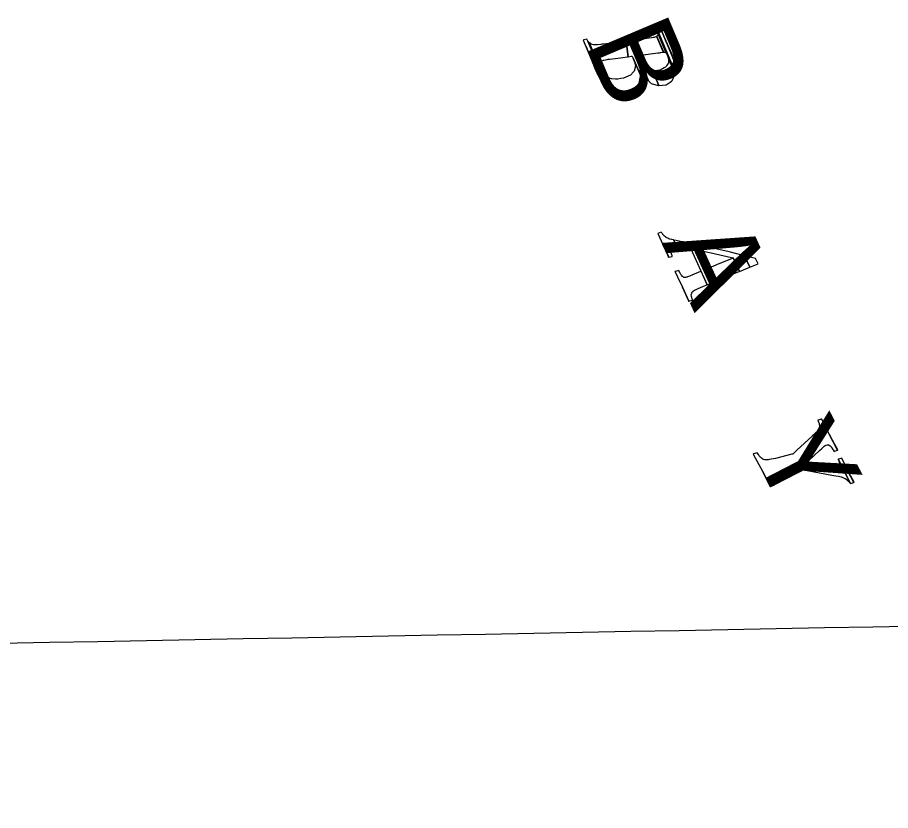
# Model space of a CAD drawing. Extents: x 3962991 to 3983549, y 181631 to 204078.
# Drawn here: x 3975675 to 3976425, y 194348 to 195029 of the extents above; entities that cross this region are included whole.
import ezdxf

# ---------------------------------------------------------------- set-up
doc = ezdxf.new("R2010")
doc.units = 0
for name, color, linetype in [('V-ANNO-MASK', 7, 'Continuous'), ('V-ANNO-MASK2', 7, 'Continuous'), ('V-GRID-MAJR', 7, 'Continuous'), ('V-RIVR-IDEN', 7, 'Continuous')]:
    doc.layers.add(name, color=color, linetype=linetype)

msp = doc.modelspace()

# ---------------------------------------------------------------- linework, layer by layer
at = {"layer": 'V-ANNO-MASK2'}
for points in [[(3976224.33, 195020.65), (3976225.16, 195018.1), (3976240.52, 194981.73), (3976240.5, 194982.35), (3976240.5, 194982.41), (3976223.81, 195021.93)], [(3976226.28, 195022.57), (3976223.82, 195021.92), (3976240.5, 194982.41), (3976240.32, 194989.32), (3976238.28, 194995.67), (3976229.42, 195016.66), (3976228.97, 195017.89), (3976227.19, 195022.8), (3976226.92, 195022.74), (3976226.86, 195022.72)], [(3976200.09, 194995.68), (3976202.73, 194996.02), (3976203.2, 194996.08), (3976203.48, 194996.11), (3976203.65, 194996.13), (3976204.46, 194994.33), (3976210.61, 194979.78), (3976210.41, 194984.09), (3976214.13, 194978.38), (3976216.68, 194975.9), (3976208.94, 194994.22), (3976207.99, 194996.61), (3976208.47, 194996.68), (3976209.74, 194996.84), (3976210.44, 194996.93), (3976214.86, 194997.5), (3976215.26, 194997.56), (3976221.3, 194998.33), (3976221.48, 194998.36), (3976225.57, 194998.89), (3976227.07, 194999.08), (3976227.71, 194999.16), (3976228.03, 194999.2), (3976230.05, 194999.46), (3976230.07, 194999.47), (3976230.69, 194999.51), (3976224.83, 195013.39), (3976224.38, 195012.93), (3976224.36, 195012.93), (3976222.52, 195012.25), (3976222.2, 195012.19), (3976221.59, 195012.07), (3976220.12, 195011.8), (3976216.03, 195011.28), (3976215.84, 195011.25), (3976209.8, 195010.47), (3976209.41, 195010.42), (3976204.99, 195009.85), (3976204.28, 195009.76), (3976203.02, 195009.59), (3976202.53, 195009.53), (3976202.48, 195009.53), (3976201.05, 195009.34), (3976199.81, 195009.18), (3976198.27, 195008.98)], [(3976224.83, 195013.39), (3976224.38, 195012.93), (3976230.07, 194999.47), (3976230.69, 194999.51), (3976231.32, 194999.55), (3976231.62, 194999.42), (3976231.61, 194999.43), (3976232.58, 194999), (3976232.84, 194998.64), (3976225.6, 195015.78), (3976225.58, 195015.57), (3976225.45, 195014.02), (3976225.28, 195013.85)], [(3976225.54, 195016.09), (3976225.6, 195015.77), (3976232.84, 194998.64), (3976233.03, 194998.36), (3976233.47, 194997.71), (3976233.66, 194997.44), (3976240.54, 194981.17), (3976240.52, 194981.73), (3976225.16, 195018.11), (3976225.34, 195017.15), (3976225.4, 195016.83)], [(3976233.8, 195006.45), (3976229.42, 195016.66), (3976238.28, 194995.68), (3976238.04, 194996.41), (3976237.5, 194998.12), (3976237.49, 194998.13)], [(3976161.45, 195010), (3976161.29, 195009.97), (3976163.83, 195004.35), (3976164.2, 195003.55), (3976174.11, 194980.08), (3976177.54, 194973.53), (3976182.23, 194968.45), (3976182.87, 194967.75), (3976165.39, 195009.14), (3976164.42, 195010.62), (3976162.08, 195010.13), (3976161.48, 195009.99)], [(3976170.58, 194987.97), (3976172.33, 194983.47), (3976173.1, 194982.02), (3976173.99, 194980.32), (3976174.11, 194980.08), (3976164.2, 195003.55), (3976168.54, 194993.22)], [(3976166.61, 195007.76), (3976165.38, 195009.15), (3976182.87, 194967.75), (3976184.06, 194966.46)], [(3976198.27, 195008.98), (3976198.22, 195008.97), (3976198.06, 195008.95), (3976197.78, 195008.92), (3976197.31, 195008.86), (3976194.66, 195008.52), (3976193.76, 195008.4), (3976190.08, 195007.93), (3976188.09, 195007.67), (3976183.48, 195007.08), (3976181.07, 195006.76), (3976178.57, 195006.43), (3976177.35, 195006.3), (3976176.45, 195006.2), (3976173.7, 195005.88), (3976173.65, 195005.88), (3976173.13, 195005.88), (3976172.08, 195005.86), (3976170.9, 195005.85), (3976170.36, 195005.83), (3976169.09, 195006.22), (3976168.53, 195006.39), (3976168.08, 195006.52), (3976167.65, 195006.88), (3976166.92, 195007.5), (3976166.81, 195007.6), (3976166.77, 195007.63), (3976166.62, 195007.75), (3976184.06, 194966.46), (3976184.24, 194966.27), (3976176.14, 194985.45), (3976176.11, 194985.57), (3976176.03, 194985.94), (3976175.51, 194988.27), (3976175.57, 194988.77), (3976175.66, 194989.5), (3976175.77, 194990.4), (3976176.51, 194991.28), (3976176.87, 194991.7), (3976177.86, 194992.18), (3976178.74, 194992.59), (3976179.21, 194992.71), (3976179.26, 194992.71), (3976181.9, 194993.31), (3976182.78, 194993.42), (3976184, 194993.58), (3976184, 194993.59), (3976186.5, 194993.91), (3976188.91, 194994.22), (3976193.52, 194994.82), (3976195.51, 194995.07), (3976195.5, 194995.08), (3976199.18, 194995.55), (3976200.09, 194995.68)], [(3976234, 194996.46), (3976234.8, 194994.16), (3976240.45, 194980.79), (3976240.54, 194980.97), (3976240.54, 194981.17), (3976233.66, 194997.44)], [(3976178.58, 194981.01), (3976177.6, 194982.22), (3976184.37, 194966.18), (3976184.95, 194965.93), (3976185.28, 194965.79), (3976185.77, 194965.57), (3976186.37, 194965.31), (3976187.73, 194964.71), (3976187.73, 194964.72), (3976188.4, 194964.42), (3976189.85, 194963.79), (3976191.15, 194963.23), (3976191.79, 194962.94), (3976191.83, 194962.95), (3976194.71, 194962.97), (3976195.65, 194962.97), (3976196.93, 194962.98), (3976199.56, 194963), (3976201.67, 194964.01), (3976205.72, 194965.94), (3976206.99, 194967.9), (3976209.34, 194971.5), (3976209.64, 194973.06), (3976210.51, 194977.6), (3976210.67, 194978.4), (3976210.63, 194979.18), (3976210.61, 194979.64), (3976210.61, 194979.78), (3976204.46, 194994.33), (3976204.71, 194993.62), (3976205.6, 194991.11), (3976205.85, 194989.82), (3976206.26, 194987.66), (3976205.33, 194983.27), (3976204.66, 194982.58), (3976201.98, 194979.76), (3976200.2, 194979.01), (3976196.08, 194977.24), (3976193.7, 194976.87), (3976191.23, 194976.46), (3976190.03, 194976.27), (3976189.05, 194976.37), (3976186.03, 194976.7), (3976185.98, 194976.7), (3976185.43, 194976.75), (3976184.33, 194976.87), (3976182.77, 194977.74), (3976182.06, 194978.13), (3976180.61, 194978.94), (3976179.97, 194979.29), (3976179.14, 194980.32)], [(3976209.17, 194993.8), (3976208.94, 194994.22), (3976216.68, 194975.9), (3976216.76, 194975.83), (3976217.64, 194974.98), (3976211.56, 194989.37)], [(3976214.06, 194986.61), (3976211.57, 194989.36), (3976217.64, 194974.98), (3976219.9, 194972.77), (3976220.76, 194972.51), (3976226.14, 194970.8), (3976226.54, 194970.84), (3976221.29, 194983.27), (3976220.81, 194983.41), (3976215.45, 194985.08)], [(3976227.31, 194984.08), (3976221.3, 194983.26), (3976226.54, 194970.84), (3976232.62, 194971.53), (3976232.77, 194971.64), (3976236.12, 194973.92), (3976237.35, 194974.76), (3976237.87, 194975.11), (3976238.04, 194975.5), (3976239.15, 194977.92), (3976239.16, 194977.95), (3976239.49, 194978.68), (3976239.82, 194979.41), (3976239.95, 194979.69), (3976240.36, 194980.59), (3976240.41, 194980.7), (3976240.45, 194980.79), (3976234.8, 194994.18), (3976234.79, 194994.01), (3976234.78, 194993.8), (3976234.7, 194992.11), (3976234.68, 194991.59), (3976234.62, 194990.21), (3976234.22, 194989.64), (3976234.21, 194989.61), (3976232.9, 194987.69), (3976232.68, 194987.37), (3976232.28, 194986.76), (3976231, 194986.06), (3976227.5, 194984.1)], [(3976176.5, 194984.65), (3976176.14, 194985.45), (3976184.24, 194966.27), (3976184.28, 194966.22), (3976184.37, 194966.18), (3976177.6, 194982.23)], [(3976225.69, 194843.84), (3976225.51, 194843.75), (3976229.97, 194834.47), (3976235.02, 194823.43), (3976237.96, 194824.21), (3976237.73, 194824.89), (3976237.49, 194825.57), (3976237.24, 194826.45), (3976237.2, 194826.59), (3976237.12, 194826.88), (3976236.87, 194827.76), (3976236.85, 194827.9), (3976236.78, 194828.71), (3976236.77, 194828.79), (3976236.68, 194829.81), (3976236.68, 194829.87), (3976236.89, 194830.45), (3976237.05, 194830.91), (3976237.17, 194831.24), (3976237.41, 194831.43), (3976237.92, 194831.79), (3976238.43, 194832.15), (3976238.51, 194832.2), (3976239.09, 194832.35), (3976240.08, 194832.59), (3976240.24, 194832.62), (3976241.6, 194832.54), (3976241.86, 194832.53), (3976239.24, 194838.25), (3976238.96, 194838.32), (3976237.45, 194838.73), (3976237.25, 194838.78), (3976236, 194839.1), (3976235.26, 194839.3), (3976235.15, 194839.34), (3976234.29, 194839.73), (3976233.43, 194840.14), (3976233.02, 194840.34), (3976232.67, 194840.5), (3976232.07, 194840.98), (3976231.32, 194841.6), (3976231.28, 194841.63), (3976230.68, 194842.12), (3976230.62, 194842.18), (3976229.95, 194843.01), (3976229.83, 194843.14), (3976229.49, 194843.56), (3976229.38, 194843.7), (3976229.32, 194843.77), (3976228.87, 194844.43), (3976228.65, 194844.75), (3976228.42, 194845.09)], [(3976241.2, 194837.84), (3976239.25, 194838.24), (3976241.86, 194832.53), (3976243.68, 194832.42), (3976248.88, 194831.65), (3976249.81, 194831.48), (3976253.92, 194830.75), (3976268.06, 194799.8), (3976272.63, 194801.71), (3976259.91, 194829.56), (3976261.86, 194829.16), (3976274.05, 194826.61), (3976275.08, 194826.37), (3976288.98, 194823.13), (3976288.98, 194823.14), (3976290.32, 194822.82), (3976295.61, 194811.25), (3976304.46, 194814.91), (3976299.95, 194824.78), (3976288.11, 194827.67), (3976286.76, 194827.99), (3976272.85, 194831.25), (3976271.82, 194831.48), (3976259.57, 194834.18), (3976257.62, 194834.56), (3976251.63, 194835.75), (3976247.49, 194836.56), (3976246.55, 194836.75)], [(3976233.91, 194825.38), (3976234.78, 194823.35), (3976234.82, 194823.37), (3976235.02, 194823.43), (3976229.97, 194834.49)], [(3976309.57, 194822.36), (3976299.95, 194824.77), (3976304.46, 194814.91), (3976311.62, 194817.89)], [(3976268.84, 194813.88), (3976267.36, 194813.25), (3976272.63, 194801.71), (3976274.12, 194802.33), (3976283.39, 194806.17), (3976284.17, 194806.49), (3976294.61, 194810.82), (3976295.61, 194811.25), (3976290.32, 194822.82), (3976289.31, 194822.41), (3976278.88, 194818.06), (3976278.1, 194817.74)], [(3976240.33, 194811.21), (3976240.26, 194811.19), (3976241.55, 194808.53), (3976242.42, 194806.75), (3976246.73, 194797.85), (3976252.32, 194785.63), (3976255.13, 194786.64), (3976255.2, 194786.66), (3976255.26, 194786.68), (3976255.39, 194786.73), (3976255.41, 194786.73), (3976255.28, 194787.14), (3976254.87, 194788.37), (3976254.73, 194788.77), (3976254.55, 194789.82), (3976254.53, 194789.91), (3976254.31, 194791.22), (3976254.32, 194791.26), (3976254.49, 194791.92), (3976254.63, 194792.43), (3976254.74, 194792.8), (3976254.86, 194793.25), (3976255.32, 194793.71), (3976255.79, 194794.17), (3976255.86, 194794.24), (3976256.3, 194794.68), (3976257.19, 194795.15), (3976257.18, 194795.16), (3976257.33, 194795.23), (3976258.4, 194795.79), (3976258.6, 194795.88), (3976260.09, 194796.5), (3976264.17, 194798.19), (3976264.88, 194798.49), (3976268.06, 194799.8), (3976262.78, 194811.36), (3976259.6, 194810.05), (3976258.89, 194809.75), (3976254.81, 194808.06), (3976253.32, 194807.44), (3976253.12, 194807.34), (3976252, 194806.88), (3976251.86, 194806.82), (3976250.91, 194806.5), (3976250.34, 194806.3), (3976250.26, 194806.27), (3976249.67, 194806.07), (3976248.99, 194806.08), (3976248.67, 194806.09), (3976248.39, 194806.09), (3976248.02, 194806.09), (3976247.36, 194806.5), (3976247.32, 194806.52), (3976246.8, 194806.84), (3976246.76, 194806.86), (3976246.09, 194807.68), (3976245.98, 194807.82), (3976245.64, 194808.23), (3976245.44, 194808.56), (3976245.34, 194808.72), (3976244.74, 194809.71), (3976244.44, 194810.2), (3976243.55, 194811.99), (3976240.6, 194811.28), (3976240.37, 194811.23)], [(3976246.73, 194797.85), (3976252.11, 194785.54), (3976252.32, 194785.63)], [(3976307.87, 194654.51), (3976307.59, 194654.4), (3976315.51, 194639.69), (3976322.32, 194626.45), (3976325.13, 194627.66), (3976325.45, 194627.78), (3976324.07, 194630.75), (3976323.33, 194632.83), (3976323.35, 194633.05), (3976323.45, 194634.63), (3976323.61, 194634.81), (3976324.5, 194635.83), (3976324.84, 194636.01), (3976325.59, 194636.39), (3976327.01, 194636.82), (3976327.62, 194636.96), (3976327.62, 194636.97), (3976333.18, 194638.22), (3976347.36, 194641.42), (3976348.21, 194641.27), (3976348.2, 194641.28), (3976353.95, 194640.24), (3976351.36, 194645.27), (3976364.36, 194657.36), (3976366.36, 194659.23), (3976367.76, 194660.52), (3976367.8, 194660.56), (3976367.79, 194660.57), (3976368.51, 194661.21), (3976369.3, 194661.66), (3976369.56, 194661.81), (3976369.88, 194661.98), (3976370.15, 194662.14), (3976371.3, 194662.4), (3976371.55, 194662.45), (3976371.74, 194662.49), (3976371.81, 194662.5), (3976373.13, 194661.83), (3976373.23, 194661.77), (3976373.44, 194661.66), (3976374.19, 194660.81), (3976374.69, 194660.24), (3976374.75, 194660.17), (3976374.88, 194660.02), (3976375.64, 194658.88), (3976375.75, 194658.72), (3976376.19, 194658.06), (3976377.05, 194656.64), (3976379.62, 194657.76), (3976379.79, 194657.83), (3976372.8, 194671.4), (3976366.48, 194684.51), (3976366.1, 194684.4), (3976365.92, 194684.36), (3976363.18, 194683.57), (3976363.07, 194683.54), (3976363.37, 194682.76), (3976363.44, 194682.57), (3976363.96, 194681.2), (3976364.11, 194680.82), (3976364.19, 194680.62), (3976364.28, 194680.04), (3976364.43, 194679.16), (3976364.5, 194678.72), (3976364.54, 194678.5), (3976364.25, 194677.17), (3976364.23, 194677.07), (3976364.17, 194676.79), (3976364.09, 194676.4), (3976363.42, 194675.21), (3976363.23, 194674.88), (3976363.02, 194674.49), (3976362.81, 194674.27), (3976362.14, 194673.57), (3976361.47, 194672.85), (3976361.44, 194672.81), (3976360.03, 194671.52), (3976358.02, 194669.67), (3976344.99, 194657.65), (3976341.45, 194654.38), (3976340.77, 194654.21), (3976326.78, 194650.66), (3976321.09, 194649.65), (3976320.42, 194649.6), (3976318.85, 194649.47), (3976317.95, 194649.38), (3976317.45, 194649.52), (3976315.83, 194649.93), (3976315.4, 194650.26), (3976313.88, 194651.43), (3976313.48, 194651.96), (3976312.44, 194653.32), (3976311.96, 194653.96), (3976310.77, 194655.53)], [(3976380.15, 194657.98), (3976372.8, 194671.4), (3976379.79, 194657.83)], [(3976380.48, 194649.99), (3976380.36, 194649.96), (3976391.09, 194629.14), (3976391.2, 194629.18), (3976393.84, 194630.15), (3976388.89, 194639.76), (3976387.1, 194643.63), (3976383.75, 194650.89), (3976383.41, 194650.8), (3976383.23, 194650.75)], [(3976372.37, 194641.81), (3976351.36, 194645.27), (3976353.95, 194640.24), (3976375.14, 194636.43), (3976378.41, 194635.84), (3976380.71, 194635.39), (3976380.77, 194635.38), (3976381.94, 194635.15), (3976383.08, 194634.92), (3976383.51, 194634.73), (3976384.04, 194634.5), (3976384.5, 194634.29), (3976386.16, 194633.55), (3976386.53, 194633.38), (3976386.8, 194633.26), (3976386.94, 194633.14), (3976388.7, 194631.59), (3976388.84, 194631.47), (3976389.12, 194631.22), (3976389.68, 194630.73), (3976390.26, 194630.01), (3976390.33, 194629.92), (3976390.48, 194629.74), (3976390.98, 194629.1), (3976391, 194629.11), (3976391.09, 194629.14), (3976380.36, 194649.97), (3976380.94, 194648.65), (3976381, 194648.49), (3976381.42, 194647.31), (3976381.55, 194646.97), (3976381.56, 194646.9), (3976381.69, 194646.25), (3976381.88, 194645.28), (3976381.98, 194644.79), (3976381.95, 194644.7), (3976381.63, 194643.44), (3976381.6, 194643.34), (3976381.53, 194643.08), (3976381.32, 194642.94), (3976380.38, 194642.3), (3976380.11, 194642.11), (3976379.74, 194642.04), (3976379.44, 194641.97), (3976378.52, 194641.78), (3976377.58, 194641.57), (3976377.52, 194641.58), (3976375.4, 194641.68)], [(3976321.14, 194628.11), (3976322.01, 194626.32), (3976322.05, 194626.34), (3976322.32, 194626.45), (3976315.51, 194639.69)], [(3976391.04, 194635.98), (3976388.89, 194639.76), (3976393.84, 194630.15), (3976394.01, 194630.21), (3976394.27, 194630.31), (3976394.27, 194630.32)]]:
    msp.add_lwpolyline(points, close=True, dxfattribs=at)
at = {"layer": 'V-GRID-MAJR'}
msp.add_spline([(3968045.99, 194348.31), (3973372.59, 194448.65), (3978699.17, 194549.76), (3978985.35, 194555.22)], degree=3, dxfattribs=at)

# ---------------------------------------------------------------- texts
at = {"layer": 'V-ANNO-MASK'}
for s, rotation, p in [('B', 292.89895, (3976162.2, 195007.76)), ('A', 294.55902, (3976229.39, 194835.98)), ('Y', 297.25534, (3976305.2, 194659.69))]:
    msp.add_text(s, height=75, rotation=rotation, dxfattribs=at).set_placement(p)
at = {"layer": 'V-RIVR-IDEN'}
for s, rotation, p in [('B', 292.89895, (3976162.2, 195007.76)), ('A', 294.55902, (3976229.39, 194835.98)), ('Y', 297.25534, (3976305.2, 194659.69))]:
    msp.add_text(s, height=75, rotation=rotation, dxfattribs=at).set_placement(p)

doc.saveas('drawing.dxf')
